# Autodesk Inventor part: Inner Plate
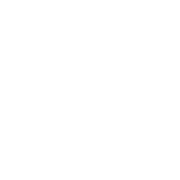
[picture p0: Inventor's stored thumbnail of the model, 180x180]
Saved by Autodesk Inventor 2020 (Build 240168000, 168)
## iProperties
Created: 2019-07
Part Number: Inner Plate
Material: Generic
Document SubType Name: Modeling
Designer: LENOVO-CADCIM
Density: 1 g/cm^3
Appearance: Default
Author: LENOVO-CADCIM
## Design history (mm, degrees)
